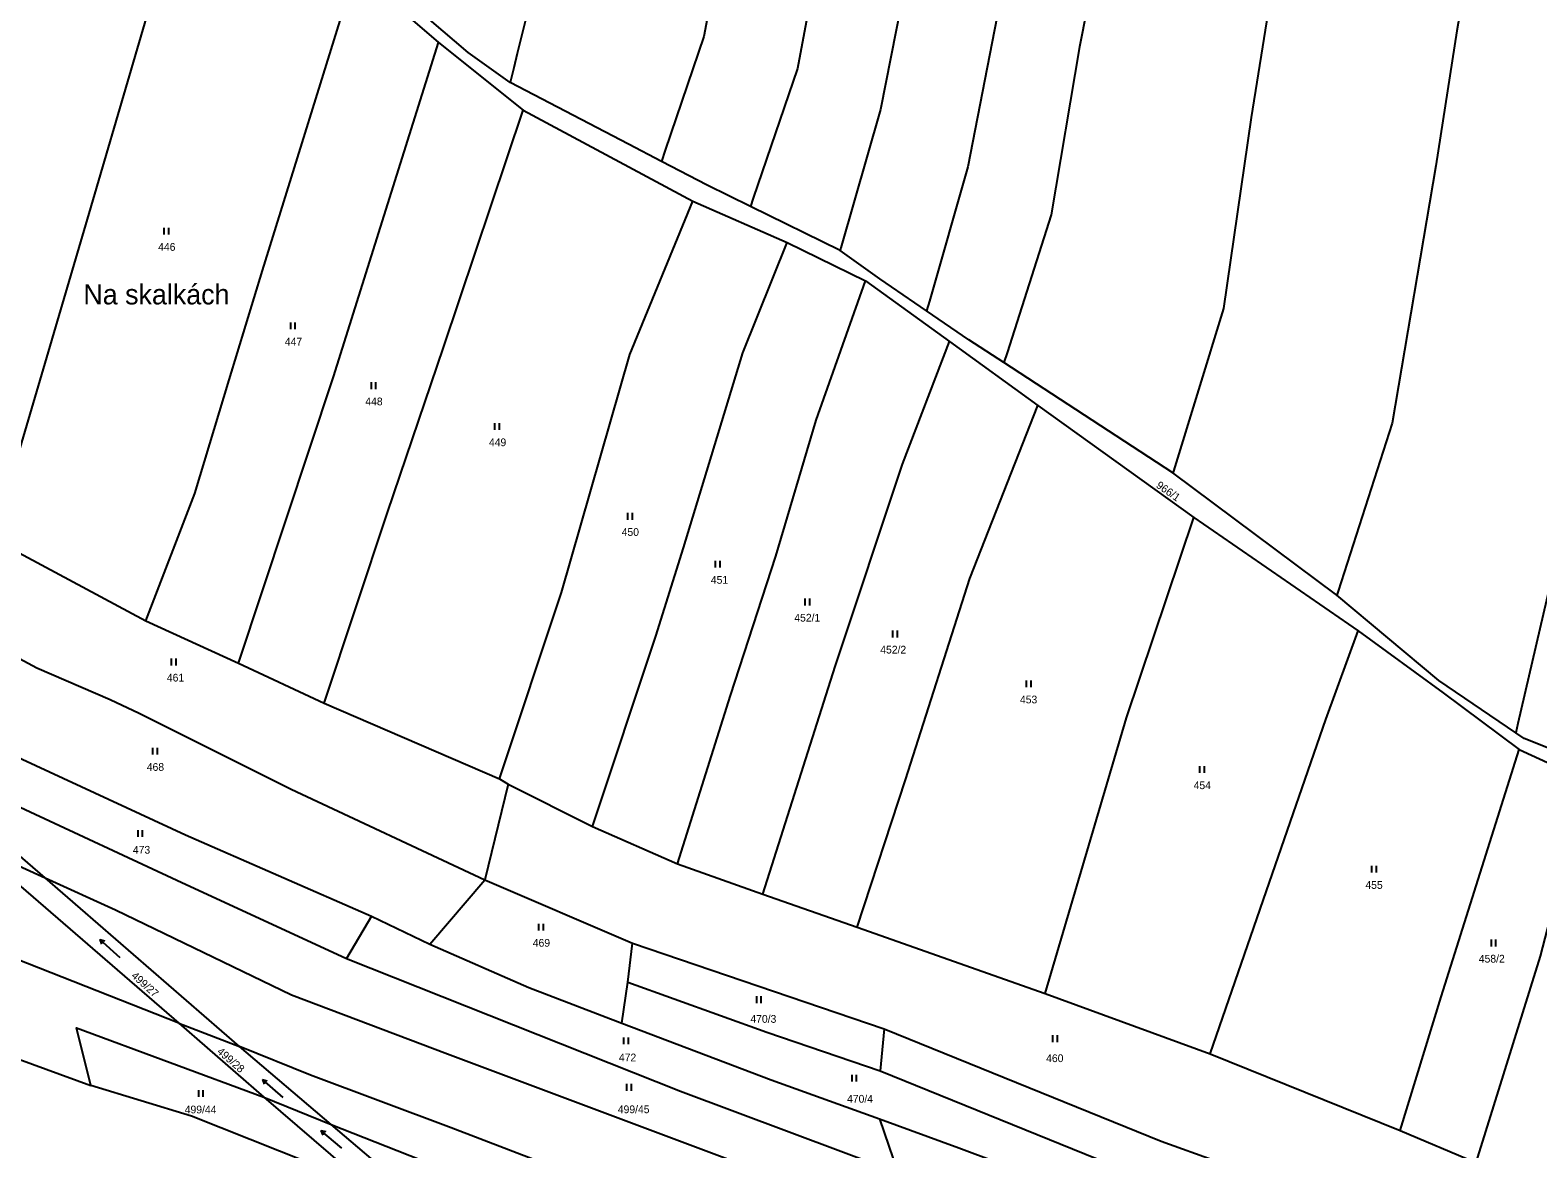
# Model space of a CAD drawing. Extents: x -7483133 to -743907, y -11317770 to -1129777.
# Drawn here: x -748488.3 to -748157.7, y -1130642.1 to -1130396.9 of the extents above; entities that cross this region are included whole.
import ezdxf

# ---------------------------------------------------------------- set-up
doc = ezdxf.new("R2010")
doc.units = 0
for name, color, linetype in [('Hranice parcel', 7, 'Continuous'), ('Parcelní čísla', 7, 'Continuous'), ('Pop  PČ popisy', 7, 'Continuous'), ('Značky kultur', 7, 'Continuous')]:
    doc.layers.add(name, color=color, linetype=linetype)

msp = doc.modelspace()

# ---------------------------------------------------------------- linework, layer by layer
at = {"layer": 'Hranice parcel'}
for p, q in [((-748416.99, -1130383.85), (-748398.74, -1130399.57)), ((-748398.74, -1130399.57), (-748380.24, -1130414.38)), ((-748380.24, -1130414.38), (-748342.98, -1130434.33)), ((-748342.98, -1130434.33), (-748322.28, -1130443.45)), ((-748310.69, -1130445.15), (-748330.38, -1130435.49)), ((-748322.28, -1130443.45), (-748305.1, -1130451.81)), ((-748305.1, -1130451.81), (-748286.73, -1130465.15)), ((-748286.73, -1130465.15), (-748267.37, -1130479.15)), ((-748237.71, -1130493.88), (-748274.78, -1130469.75)), ((-748267.37, -1130479.15), (-748233.17, -1130503.73)), ((-748201.78, -1130520.76), (-748237.71, -1130493.88)), ((-748233.17, -1130503.73), (-748197.06, -1130528.56)), ((-748498.16, -1130507.52), (-748462.95, -1130526.39)), ((-748462.95, -1130526.39), (-748442.63, -1130535.63)), ((-748442.63, -1130535.63), (-748423.83, -1130544.43)), ((-748423.83, -1130544.43), (-748385.43, -1130560.99)), ((-748161.77, -1130554.58), (-748147.15, -1130561.27)), ((-748383.52, -1130562.14), (-748388.62, -1130583.11)), ((-748385.43, -1130560.99), (-748383.52, -1130562.14)), ((-748383.52, -1130562.14), (-748365.02, -1130571.43)), ((-748365.02, -1130571.43), (-748346.39, -1130579.64)), ((-748501.01, -1130575.41), (-748485.04, -1130582.73)), ((-748501.01, -1130575.41), (-748455.69, -1130614.55)), ((-748346.39, -1130579.64), (-748327.67, -1130586.29)), ((-748442.43, -1130619.67), (-748485.04, -1130582.73)), ((-748400.65, -1130597.24), (-748388.62, -1130583.11)), ((-748388.62, -1130583.11), (-748356.21, -1130597)), ((-748327.67, -1130586.29), (-748306.94, -1130593.5)), ((-748413.5, -1130591.12), (-748418.92, -1130600.37)), ((-748413.5, -1130591.12), (-748400.65, -1130597.24)), ((-748306.94, -1130593.5), (-748265.75, -1130608.04)), ((-748357.28, -1130605.56), (-748356.21, -1130597)), ((-748356.21, -1130597), (-748301.06, -1130615.84)), ((-748358.56, -1130614.59), (-748357.28, -1130605.56)), ((-748265.75, -1130608.04), (-748229.57, -1130621.28)), ((-748455.69, -1130614.55), (-748442.43, -1130619.67)), ((-748455.69, -1130614.55), (-748437.09, -1130630.78)), ((-748301.06, -1130615.84), (-748301.92, -1130625.04)), ((-748422.31, -1130636.78), (-748442.43, -1130619.67)), ((-748229.57, -1130621.28), (-748187.91, -1130638.09)), ((-748301.92, -1130625.04), (-748240.56, -1130649.85)), ((-748437.09, -1130630.78), (-748422.31, -1130636.78)), ((-748437.09, -1130630.78), (-748414.36, -1130650.31)), ((-748399.6, -1130656.07), (-748422.31, -1130636.78)), ((-748302.08, -1130635.58), (-748298.06, -1130647.31)), ((-748187.91, -1130638.09), (-748171.3, -1130645.09))]:
    msp.add_line(p, q, dxfattribs=at)
for points in [[(-748313.47, -1130024.7), (-748324.42, -1130066.78), (-748323.17, -1130071.99), (-748329.49, -1130091.24), (-748330.95, -1130098.96), (-748334.93, -1130119.04), (-748347.33, -1130213.56), (-748354.56, -1130266.17), (-748358.56, -1130287.5), (-748375.61, -1130378.2), (-748381.5, -1130402.01), (-748382.27, -1130405.12), (-748383.06, -1130408.32)], [(-748279.89, -1130046.34), (-748290.45, -1130083.32), (-748301.44, -1130157.87), (-748310.75, -1130225.84), (-748318.01, -1130275.6), (-748323.08, -1130307.15), (-748327.81, -1130334.64), (-748335.7, -1130372.24), (-748340.62, -1130398.27), (-748349.04, -1130423.2), (-748349.86, -1130425.63)], [(-748130.22, -1130087.61), (-748131.13, -1130105.98), (-748132.47, -1130123.43), (-748138.48, -1130165.82), (-748139.67, -1130175.32), (-748144.94, -1130218.98), (-748149.15, -1130242.84), (-748155.25, -1130281.49), (-748166.79, -1130346.74), (-748175.48, -1130397.01), (-748180.06, -1130426.59), (-748189.62, -1130483.05), (-748201.5, -1130519.88), (-748201.78, -1130520.76)], [(-748169.91, -1130092.32), (-748177.35, -1130147.37), (-748182.55, -1130189.99), (-748186.18, -1130220.14), (-748188.49, -1130234.32), (-748193.97, -1130267.58), (-748201.44, -1130315.33), (-748212.24, -1130367.23), (-748215.27, -1130383.11), (-748220.54, -1130416.01), (-748226.63, -1130457.88), (-748237.61, -1130493.57), (-748237.71, -1130493.88)], [(-748273.39, -1130097.24), (-748281.27, -1130156.73), (-748287.31, -1130202.54), (-748290.79, -1130232.85), (-748299.54, -1130289.08), (-748301.91, -1130302.35), (-748302.4, -1130309.37), (-748305.11, -1130326.61), (-748309.55, -1130348.99), (-748320.05, -1130405.29), (-748329.77, -1130433.7), (-748330.38, -1130435.49)], [(-748252.59, -1130102.61), (-748256.07, -1130126.15), (-748263.51, -1130176.19), (-748266.5, -1130195.5), (-748271.15, -1130229.91), (-748277.05, -1130270.85), (-748279.2, -1130292.94), (-748282.82, -1130314.7), (-748292.75, -1130368.29), (-748301.85, -1130414.23), (-748310.54, -1130444.61), (-748310.69, -1130445.15)], [(-748230.76, -1130101.5), (-748238.92, -1130155.41), (-748244.23, -1130193.64), (-748250.06, -1130231.72), (-748257.56, -1130283.34), (-748263.19, -1130320.1), (-748266.04, -1130338.03), (-748272.57, -1130374.93), (-748282.67, -1130426.83), (-748291.12, -1130456.26), (-748291.74, -1130458.41)], [(-748211.28, -1130100.51), (-748218.94, -1130146.82), (-748219.36, -1130157.24), (-748223.16, -1130188.85), (-748229.48, -1130229.5), (-748236.23, -1130271.46), (-748240.43, -1130308.77), (-748250.12, -1130359.49), (-748258.18, -1130400.55), (-748264.43, -1130437.38), (-748274.1, -1130467.62), (-748274.78, -1130469.75)], [(-748097.23, -1130149.25), (-748104.99, -1130205.45), (-748110.44, -1130246.87), (-748117.05, -1130286.59), (-748125.58, -1130341), (-748144.02, -1130456.52), (-748151, -1130501.06), (-748162.06, -1130548.84), (-748162.54, -1130550.9)], [(-748491.6, -1130492.22), (-748475.41, -1130437.09), (-748455.96, -1130370.65), (-748448.4, -1130345.8)], [(-748462.95, -1130526.39), (-748452.24, -1130498.41), (-748444.7, -1130473.49), (-748437.34, -1130449.55), (-748416.99, -1130383.85)], [(-748383.06, -1130408.32), (-748392.3, -1130401.74), (-748400.76, -1130394.53)], [(-748442.63, -1130535.63), (-748421.81, -1130472.84), (-748398.74, -1130399.57)], [(-748349.86, -1130425.63), (-748357.14, -1130421.83), (-748383.06, -1130408.32)], [(-748423.83, -1130544.43), (-748409.99, -1130502.63), (-748397.69, -1130466.45), (-748380.24, -1130414.38)], [(-748330.38, -1130435.49), (-748339.87, -1130430.84), (-748349.86, -1130425.63)], [(-748385.43, -1130560.99), (-748371.83, -1130520.13), (-748356.78, -1130467.99), (-748342.98, -1130434.33)], [(-748365.02, -1130571.43), (-748351.1, -1130529.74), (-748345.06, -1130510.33), (-748332.01, -1130467.6), (-748322.28, -1130443.45)], [(-748291.74, -1130458.41), (-748301.96, -1130451.39), (-748310.69, -1130445.15)], [(-748346.39, -1130579.64), (-748334.71, -1130542.76), (-748324.77, -1130512.21), (-748315.97, -1130482.36), (-748305.1, -1130451.81)], [(-748274.78, -1130469.75), (-748282.46, -1130464.75), (-748291.74, -1130458.41)], [(-748327.67, -1130586.29), (-748311.77, -1130536.36), (-748297.02, -1130491.98), (-748286.73, -1130465.15)], [(-748306.94, -1130593.5), (-748296.39, -1130561.23), (-748282.24, -1130517.07), (-748267.37, -1130479.15)], [(-748265.75, -1130608.04), (-748247.9, -1130547.61), (-748233.17, -1130503.73)], [(-748526.29, -1130515.48), (-748486.84, -1130536.66), (-748470.75, -1130543.61), (-748464.43, -1130546.57), (-748431.07, -1130563.27), (-748388.62, -1130583.11)], [(-748162.54, -1130550.9), (-748179.44, -1130539.41), (-748201.78, -1130520.76)], [(-748229.57, -1130621.28), (-748216.56, -1130583.68), (-748204.16, -1130547.99), (-748197.06, -1130528.56)], [(-748197.06, -1130528.56), (-748178.46, -1130542.16), (-748161.77, -1130554.58)], [(-748516.42, -1130541.69), (-748493.99, -1130554.85), (-748454.25, -1130573.29), (-748413.5, -1130591.12)], [(-748147.44, -1130557.42), (-748160.67, -1130552.17), (-748162.54, -1130550.9)], [(-748511.31, -1130555.77), (-748507.24, -1130559.45), (-748489.41, -1130567.71), (-748456.16, -1130583.21), (-748418.92, -1130600.37)], [(-748187.91, -1130638.09), (-748178.92, -1130608.81), (-748161.77, -1130554.58)], [(-748147.15, -1130561.27), (-748157.21, -1130599.87), (-748171.3, -1130645.09)], [(-748485.04, -1130582.73), (-748503.04, -1130567.18), (-748505.94, -1130571.16), (-748501.01, -1130575.41)], [(-748455.69, -1130614.55), (-748519.76, -1130589.35), (-748557.39, -1130573.5)], [(-748485.04, -1130582.73), (-748469.61, -1130589.74), (-748431.04, -1130608.33), (-748396.79, -1130621.28), (-748326.64, -1130647.59), (-748273.31, -1130666.87), (-748248.94, -1130675.02), (-748226.83, -1130683.61)], [(-748569.31, -1130592.51), (-748523.25, -1130610.65), (-748474.99, -1130628.2)], [(-748400.65, -1130597.24), (-748378.93, -1130606.77), (-748358.56, -1130614.59)], [(-748418.92, -1130600.37), (-748345.69, -1130629.51), (-748298.06, -1130647.31)], [(-748357.28, -1130605.56), (-748326.8, -1130616.53), (-748301.92, -1130625.04)], [(-748358.56, -1130614.59), (-748325.84, -1130627.02), (-748302.08, -1130635.58)], [(-748474.99, -1130628.2), (-748478.16, -1130615.62), (-748437.09, -1130630.78)], [(-748301.06, -1130615.84), (-748240.31, -1130640.44), (-748203.71, -1130653.58), (-748161.84, -1130668.98)], [(-748280.18, -1130682.27), (-748326.88, -1130664.57), (-748359.23, -1130651.59), (-748396.02, -1130637.54), (-748426.83, -1130625.94), (-748442.43, -1130619.67)], [(-748414.36, -1130650.31), (-748452.93, -1130634.95), (-748474.99, -1130628.2)], [(-748422.31, -1130636.78), (-748358.85, -1130661.76), (-748278.6, -1130693.52)], [(-748302.08, -1130635.58), (-748284.66, -1130641.91), (-748243.24, -1130657.42)]]:
    msp.add_lwpolyline(points, dxfattribs=at)
at = {"layer": 'Značky kultur'}
for p, q in [((-748458.93, -1130441.68), (-748458.93, -1130440.18)), ((-748457.93, -1130441.68), (-748457.93, -1130440.18)), ((-748431.19, -1130462.45), (-748431.19, -1130460.95)), ((-748430.19, -1130462.45), (-748430.19, -1130460.95)), ((-748413.49, -1130475.56), (-748413.49, -1130474.06)), ((-748412.49, -1130475.56), (-748412.49, -1130474.06)), ((-748386.39, -1130484.52), (-748386.39, -1130483.02)), ((-748385.39, -1130484.52), (-748385.39, -1130483.02)), ((-748357.22, -1130504.19), (-748357.22, -1130502.69)), ((-748356.22, -1130504.19), (-748356.22, -1130502.69)), ((-748338, -1130514.68), (-748338, -1130513.18)), ((-748337, -1130514.68), (-748337, -1130513.18)), ((-748318.33, -1130522.98), (-748318.33, -1130521.48)), ((-748317.33, -1130522.98), (-748317.33, -1130521.48)), ((-748299.11, -1130529.98), (-748299.11, -1130528.48)), ((-748298.11, -1130529.98), (-748298.11, -1130528.48)), ((-748457.33, -1130536.12), (-748457.33, -1130534.62)), ((-748456.33, -1130536.12), (-748456.33, -1130534.62)), ((-748269.83, -1130540.91), (-748269.83, -1130539.41)), ((-748268.83, -1130540.91), (-748268.83, -1130539.41)), ((-748461.41, -1130555.7), (-748461.41, -1130554.2)), ((-748460.41, -1130555.7), (-748460.41, -1130554.2)), ((-748231.81, -1130559.71), (-748231.81, -1130558.21)), ((-748230.81, -1130559.71), (-748230.81, -1130558.21)), ((-748464.67, -1130573.74), (-748464.67, -1130572.24)), ((-748463.67, -1130573.74), (-748463.67, -1130572.24)), ((-748194.11, -1130581.57), (-748194.11, -1130580.07)), ((-748193.11, -1130581.57), (-748193.11, -1130580.07)), ((-748376.78, -1130594.26), (-748376.78, -1130592.76)), ((-748375.78, -1130594.26), (-748375.78, -1130592.76)), ((-748468.58, -1130600.25), (-748473.04, -1130596.24)), ((-748473.04, -1130596.24), (-748472.65, -1130597.26)), ((-748473.04, -1130596.24), (-748471.97, -1130596.52)), ((-748167.89, -1130597.74), (-748167.89, -1130596.24)), ((-748166.89, -1130597.74), (-748166.89, -1130596.24)), ((-748329, -1130610.17), (-748329, -1130608.67)), ((-748328, -1130610.17), (-748328, -1130608.67)), ((-748358.11, -1130619.19), (-748358.11, -1130617.69)), ((-748357.11, -1130619.19), (-748357.11, -1130617.69)), ((-748264.03, -1130618.7), (-748264.03, -1130617.2)), ((-748263.03, -1130618.7), (-748263.03, -1130617.2)), ((-748432.86, -1130630.87), (-748437.39, -1130626.93)), ((-748437.39, -1130626.93), (-748436.98, -1130627.95)), ((-748437.39, -1130626.93), (-748436.33, -1130627.2)), ((-748357.48, -1130629.4), (-748357.48, -1130627.9)), ((-748356.48, -1130629.4), (-748356.48, -1130627.9)), ((-748308.08, -1130627.38), (-748308.08, -1130625.88)), ((-748307.08, -1130627.38), (-748307.08, -1130625.88)), ((-748451.36, -1130630.74), (-748451.36, -1130629.24)), ((-748450.36, -1130630.74), (-748450.36, -1130629.24)), ((-748419.96, -1130641.96), (-748424.56, -1130638.1)), ((-748424.56, -1130638.1), (-748424.13, -1130639.12)), ((-748424.56, -1130638.1), (-748423.48, -1130638.35))]:
    msp.add_line(p, q, dxfattribs=at)

# ---------------------------------------------------------------- texts
at = {"layer": 'Parcelní čísla'}
for s, p in [('446', (-748460.25, -1130445.23)), ('447', (-748432.47, -1130466)), ('448', (-748414.82, -1130479.11)), ('449', (-748387.71, -1130488.07)), ('450', (-748358.6, -1130507.74)), ('451', (-748339.05, -1130518.23)), ('452/1', (-748320.75, -1130526.53)), ('452/2', (-748301.9, -1130533.53)), ('461', (-748458.34, -1130539.67)), ('453', (-748271.26, -1130544.46)), ('468', (-748462.74, -1130559.25)), ('454', (-748233.17, -1130563.26)), ('473', (-748465.79, -1130577.41)), ('455', (-748195.51, -1130585.12)), ('469', (-748378.1, -1130597.81)), ('458/2', (-748170.64, -1130601.29)), ('470/3', (-748330.38, -1130614.49)), ('472', (-748359.21, -1130622.94)), ('460', (-748265.52, -1130623.11)), ('470/4', (-748309.18, -1130632)), ('499/44', (-748454.42, -1130634.35)), ('499/45', (-748359.45, -1130634.31))]:
    msp.add_text(s, height=1.7, dxfattribs=at).set_placement(p)
for s, rotation, p in [('966/1', 325, (-748241.55, -1130497)), ('499/27', 318, (-748466.26, -1130604.38)), ('499/28', 319, (-748447.48, -1130621.01))]:
    msp.add_text(s, height=1.7, rotation=rotation, dxfattribs=at).set_placement(p)
at = {"layer": 'Pop  PČ popisy'}
msp.add_text('Na skalkách', height=4.4, dxfattribs=at).set_placement((-748476.65, -1130456.99))

doc.saveas('drawing.dxf')
